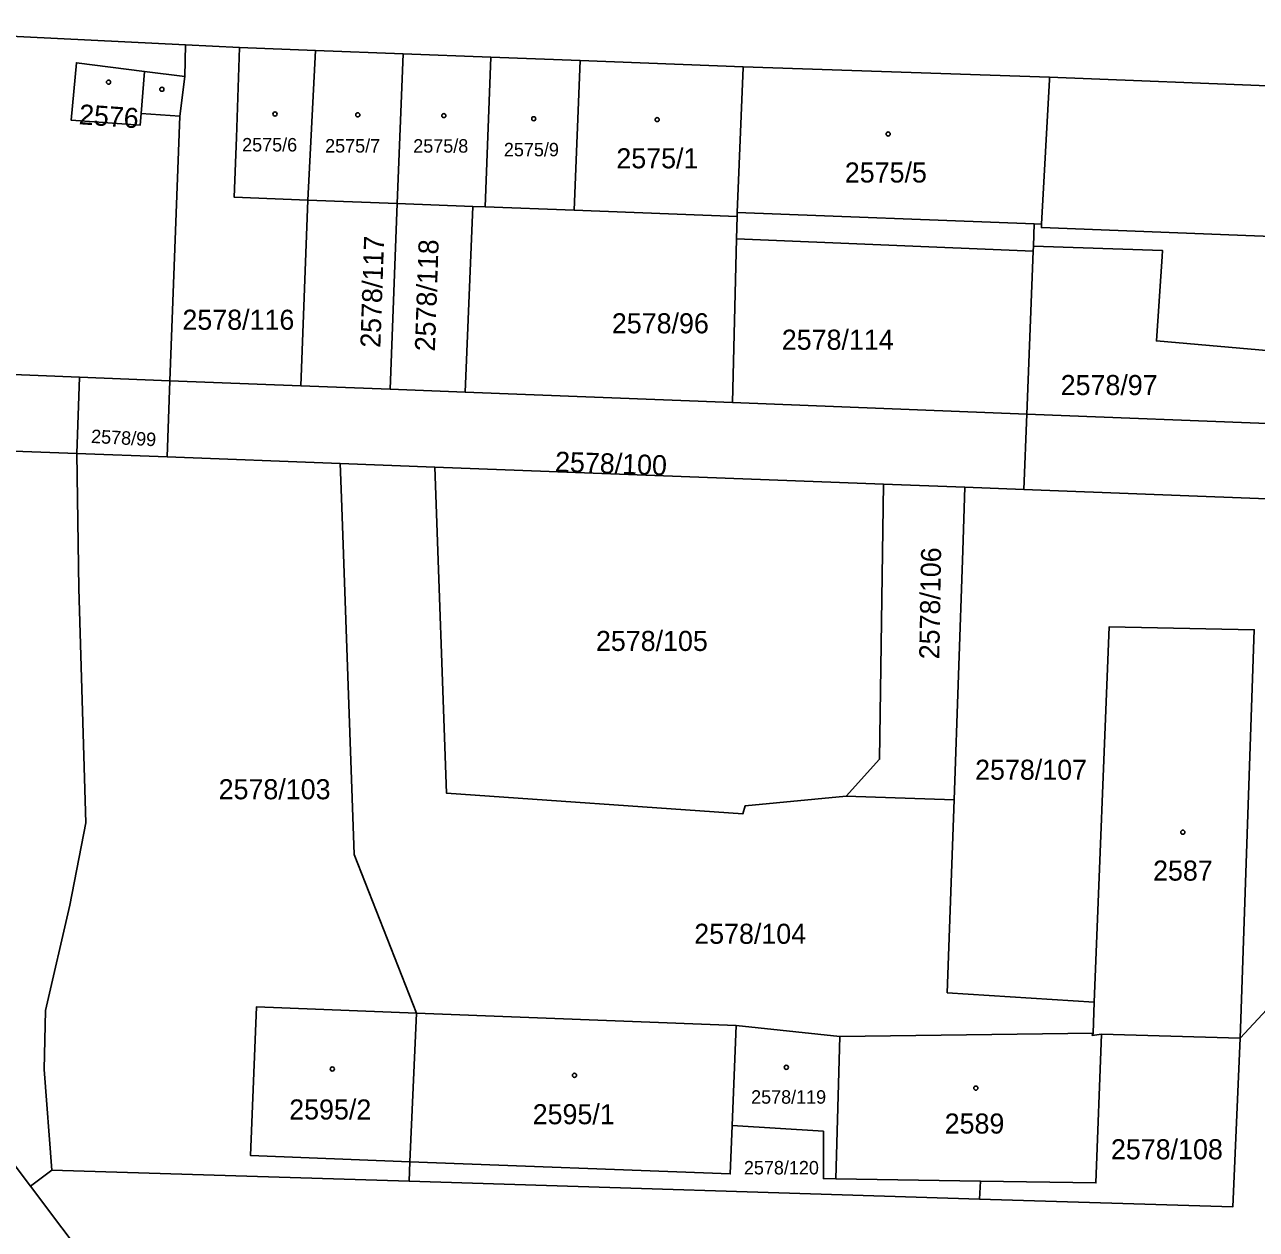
# Model space of a CAD drawing. Extents: x -527335 to -526256, y -1079142 to -1077809.
# Drawn here: x -526804.7 to -526700.3, y -1078353.9 to -1078251.9 of the extents above; entities that cross this region are included whole.
import ezdxf

# ---------------------------------------------------------------- set-up
doc = ezdxf.new("R2010")
doc.units = 0
for name, color, linetype in [('Vrstva 1', 7, 'Continuous'), ('Vrstva 2', 7, 'Continuous'), ('Vrstva 4', 7, 'Continuous'), ('Vrstva 5', 7, 'Continuous')]:
    doc.layers.add(name, color=color, linetype=linetype)

msp = doc.modelspace()

# ---------------------------------------------------------------- linework, layer by layer
at = {"layer": 'Vrstva 1'}
for p, q in [((-526826.23, -1078251.91), (-526791.08, -1078253.62)), ((-526791.14, -1078256.3), (-526791.08, -1078253.62)), ((-526791.08, -1078253.62), (-526786.5, -1078253.84)), ((-526786.5, -1078253.84), (-526780.07, -1078254.09)), ((-526780.72, -1078266.76), (-526780.07, -1078254.09)), ((-526780.07, -1078254.09), (-526772.64, -1078254.38)), ((-526773.14, -1078267.05), (-526772.64, -1078254.38)), ((-526772.64, -1078254.38), (-526765.2, -1078254.66)), ((-526765.7, -1078267.34), (-526765.2, -1078254.66)), ((-526765.2, -1078254.66), (-526757.63, -1078254.96)), ((-526757.63, -1078254.96), (-526758.15, -1078267.63)), ((-526757.63, -1078254.96), (-526743.82, -1078255.49)), ((-526743.82, -1078255.49), (-526717.88, -1078256.37)), ((-526791.56, -1078259.67), (-526791.14, -1078256.3)), ((-526717.88, -1078256.37), (-526675.26, -1078258.03)), ((-526792.4, -1078282.06), (-526791.56, -1078259.67)), ((-526781.3, -1078282.49), (-526780.72, -1078266.76)), ((-526780.72, -1078266.76), (-526773.14, -1078267.05)), ((-526773.73, -1078282.79), (-526773.14, -1078267.05)), ((-526773.14, -1078267.05), (-526766.73, -1078267.3)), ((-526766.73, -1078267.3), (-526767.38, -1078283.04)), ((-526765.7, -1078267.34), (-526766.73, -1078267.3)), ((-526758.15, -1078267.63), (-526765.7, -1078267.34)), ((-526758.15, -1078267.63), (-526744.34, -1078268.16)), ((-526744.38, -1078270.05), (-526744.34, -1078268.16)), ((-526744.74, -1078283.92), (-526744.38, -1078270.05)), ((-526744.38, -1078270.05), (-526719.25, -1078271.09)), ((-526719.25, -1078271.09), (-526719.79, -1078284.89)), ((-526719.23, -1078270.66), (-526719.25, -1078271.09)), ((-526827.32, -1078280.7), (-526800.05, -1078281.76)), ((-526800.3, -1078288.23), (-526800.05, -1078281.76)), ((-526800.05, -1078281.76), (-526792.4, -1078282.06)), ((-526792.64, -1078288.52), (-526792.4, -1078282.06)), ((-526781.3, -1078282.49), (-526792.4, -1078282.06)), ((-526773.73, -1078282.79), (-526781.3, -1078282.49)), ((-526767.38, -1078283.04), (-526773.73, -1078282.79)), ((-526767.38, -1078283.04), (-526744.74, -1078283.92)), ((-526719.79, -1078284.89), (-526744.74, -1078283.92)), ((-526720.03, -1078291.28), (-526719.79, -1078284.89)), ((-526719.79, -1078284.89), (-526695.92, -1078285.82)), ((-526800.3, -1078288.23), (-526792.64, -1078288.52)), ((-526792.64, -1078288.52), (-526777.97, -1078289.08)), ((-526777.97, -1078289.08), (-526769.95, -1078289.38)), ((-526769.95, -1078289.38), (-526731.94, -1078290.83)), ((-526731.94, -1078290.83), (-526725.04, -1078291.09)), ((-526725.04, -1078291.09), (-526720.03, -1078291.28)), ((-526720.03, -1078291.28), (-526692.39, -1078292.33)), ((-526725.95, -1078317.56), (-526735.11, -1078317.24)), ((-526693.43, -1078328.83), (-526701.71, -1078337.73)), ((-526714.17, -1078337.31), (-526714.07, -1078334.69)), ((-526771.51, -1078335.61), (-526772.06, -1078348.2)), ((-526771.51, -1078335.61), (-526744.43, -1078336.68)), ((-526744.76, -1078345.14), (-526744.43, -1078336.68)), ((-526744.43, -1078336.68), (-526735.62, -1078337.6)), ((-526735.62, -1078337.6), (-526735.98, -1078349.65)), ((-526735.62, -1078337.6), (-526714.17, -1078337.31)), ((-526701.71, -1078337.73), (-526713.46, -1078337.4)), ((-526772.13, -1078349.86), (-526772.06, -1078348.2)), ((-526802.4, -1078348.91), (-526804.2, -1078350.27)), ((-526772.13, -1078349.86), (-526802.4, -1078348.91)), ((-526735.98, -1078349.65), (-526723.71, -1078349.84)), ((-526723.81, -1078351.38), (-526772.13, -1078349.86)), ((-526723.71, -1078349.84), (-526723.81, -1078351.38))]:
    msp.add_line(p, q, dxfattribs=at)
for points in [[(-526786.5, -1078253.84), (-526786.77, -1078261.47), (-526786.95, -1078266.52), (-526780.72, -1078266.76)], [(-526791.14, -1078256.3), (-526794.56, -1078255.87), (-526800.32, -1078255.14), (-526800.76, -1078260.01), (-526794.92, -1078260.41), (-526794.85, -1078259.43), (-526791.56, -1078259.67)], [(-526744.34, -1078268.16), (-526744.32, -1078267.82), (-526743.83, -1078255.55), (-526743.82, -1078255.49)], [(-526717.88, -1078256.37), (-526717.88, -1078256.55), (-526718.54, -1078268.81)], [(-526718.54, -1078268.81), (-526718.55, -1078269.1), (-526675.94, -1078270.75), (-526675.26, -1078258.03)], [(-526718.54, -1078268.81), (-526719.16, -1078268.79), (-526719.23, -1078270.66)], [(-526719.23, -1078270.66), (-526708.29, -1078271.04), (-526708.33, -1078271.55), (-526708.81, -1078278.7), (-526695.63, -1078279.84), (-526695.81, -1078283.53)], [(-526842.74, -1078286.62), (-526817.12, -1078287.6), (-526800.3, -1078288.23)], [(-526804.2, -1078350.27), (-526821.9, -1078326.75), (-526841.53, -1078291.28), (-526842.74, -1078286.62)], [(-526802.4, -1078348.91), (-526803.06, -1078340.39), (-526802.94, -1078335.4), (-526800.87, -1078326.48), (-526799.53, -1078319.5), (-526800.12, -1078299.66), (-526800.3, -1078288.23)], [(-526771.51, -1078335.61), (-526776.79, -1078322.2), (-526777.86, -1078291.99), (-526777.97, -1078289.08)], [(-526735.11, -1078317.24), (-526743.65, -1078318.06), (-526743.85, -1078318.74), (-526768.97, -1078316.99), (-526769.95, -1078289.38)], [(-526735.11, -1078317.24), (-526732.26, -1078314.12), (-526731.94, -1078290.83)], [(-526725.95, -1078317.56), (-526725.21, -1078296.43), (-526725.04, -1078291.09)], [(-526714.07, -1078334.69), (-526712.81, -1078302.9), (-526700.52, -1078303.16), (-526701.71, -1078337.73)], [(-526714.07, -1078334.69), (-526726.53, -1078333.89), (-526725.95, -1078317.56)], [(-526772.06, -1078348.2), (-526785.56, -1078347.68), (-526785.06, -1078335.08), (-526771.51, -1078335.61)], [(-526701.71, -1078337.73), (-526702.34, -1078352.03), (-526723.81, -1078351.38)], [(-526713.46, -1078337.4), (-526713.93, -1078350), (-526723.71, -1078349.84)], [(-526714.17, -1078337.31), (-526714.24, -1078337.52), (-526713.46, -1078337.4)], [(-526772.06, -1078348.2), (-526744.92, -1078349.24), (-526744.76, -1078345.14)], [(-526744.76, -1078345.14), (-526737.02, -1078345.63), (-526737.03, -1078349.63), (-526735.98, -1078349.65)], [(-526761.68, -1078404.12), (-526793.59, -1078364.38), (-526804.2, -1078350.27)]]:
    msp.add_lwpolyline(points, dxfattribs=at)
at = {"layer": 'Vrstva 4'}
for p, q in [((-526794.56, -1078255.87), (-526794.85, -1078259.43)), ((-526744.32, -1078267.82), (-526719.16, -1078268.79))]:
    msp.add_line(p, q, dxfattribs=at)
at = {"layer": 'Vrstva 5'}
for centre in [(-526797.6, -1078256.78), (-526793.08, -1078257.38), (-526783.5, -1078259.48), (-526776.48, -1078259.55), (-526769.19, -1078259.61), (-526761.57, -1078259.88), (-526751.11, -1078259.95), (-526731.54, -1078261.17), (-526706.57, -1078320.3), (-526778.64, -1078340.35), (-526740.17, -1078340.21), (-526758.12, -1078340.89), (-526724.11, -1078341.97)]:
    msp.add_circle(centre, 0.175, dxfattribs=at)

# ---------------------------------------------------------------- texts
at = {"layer": 'Vrstva 2'}
for s, height, rotation, p in [('2576', 1.7, 356, (-526800.15, -1078260.34)), ('2578/117', 1.7, 88, (-526774.57, -1078279.3)), ('2578/118', 1.7, 88, (-526769.95, -1078279.6)), ('2578/99', 1.14, 357, (-526799.1, -1078287.33)), ('2578/100', 1.7, 358, (-526759.79, -1078289.76)), ('2578/106', 1.7, 89, (-526727.21, -1078305.67))]:
    msp.add_text(s, height=height, rotation=rotation, dxfattribs=at).set_placement(p)
for s, height, p in [('2575/6', 1.14, (-526786.28, -1078262.65)), ('2575/7', 1.14, (-526779.25, -1078262.74)), ('2575/8', 1.14, (-526771.78, -1078262.75)), ('2575/9', 1.14, (-526764.1, -1078263.06)), ('2575/1', 1.7, (-526754.57, -1078264.08)), ('2575/5', 1.7, (-526735.21, -1078265.28)), ('2578/116', 1.7, (-526791.34, -1078277.75)), ('2578/96', 1.7, (-526754.95, -1078278.05)), ('2578/114', 1.7, (-526740.55, -1078279.44)), ('2578/97', 1.7, (-526716.92, -1078283.28)), ('2578/105', 1.7, (-526756.3, -1078304.95)), ('2578/107', 1.7, (-526724.17, -1078315.86)), ('2578/103', 1.7, (-526788.27, -1078317.51)), ('2587', 1.7, (-526709.09, -1078324.4)), ('2578/104', 1.7, (-526747.97, -1078329.75)), ('2578/119', 1.139, (-526743.15, -1078343.29)), ('2595/2', 1.7, (-526782.29, -1078344.63)), ('2595/1', 1.7, (-526761.66, -1078345.03)), ('2589', 1.7, (-526726.75, -1078345.82)), ('2578/108', 1.7, (-526712.66, -1078348)), ('2578/120', 1.139, (-526743.76, -1078349.28))]:
    msp.add_text(s, height=height, dxfattribs=at).set_placement(p)

doc.saveas('drawing.dxf')
